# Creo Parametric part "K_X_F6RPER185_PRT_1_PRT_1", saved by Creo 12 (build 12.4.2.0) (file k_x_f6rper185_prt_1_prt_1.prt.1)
Units: Custom; MM, KILOGRAM, SECS

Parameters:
  PTC_WM_ITERATION = "0"
  PTC_WM_VERSION = "-.0"
  PTC_WM_LIFECYCLE_STATE = "In Work"
  PTC_WM_LIFECYCLE = "MO_CADDocument"
  PTC_WM_CREATED_BY = "Maximilian Roepper (Z0017RMS: MO)"
  PTC_WM_CREATED_ON = "18-Sep-26 11:36:42 AM"
  PTC_WM_MODIFIED_BY = "Maximilian Roepper (Z0017RMS: MO)"
  PTC_WM_MODIFIED_ON = "18-Sep-26 11:36:46 AM"
  PDMLINKNUMBER = "PDM000071455158"
  PTC_WM_NAME = "k_x_f6rper185_prt_1_prt_1.prt"
  PTC_WM_NUMBER = "PDM000071455158"

Other parameters: WEIGHT, WEIGHT_FACTOR, WEIGHT_ADD, _MASS_TEMP, _DIFF_TEMP, MC_ERRORS, SUPPLIER

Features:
  1. coordinate system
  2. datum plane "PRT_YZ"
  3. datum plane "PRT_XY"
  4. datum plane "PRT_XZ"
  5. coordinate system
  6. datum axis
  7. datum axis
  8. datum axis
  9. coordinate system
  10. imported feature
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
Other named items: PRT, SIEMENS_MO, DRW_VIEW_ORG, PRT_X, PRT_Y, PRT_Z, CS0, ROUGH_GROB

Layers: 00_STD_CSYS-KSYS, 01_STD_PLANES-EBENEN, 02_STD_AXES-ACHSEN, 03_STD_CSYS-KSYS, 24_IMPORT_FEAT-IMPORT_KE

Surfaces: 16 tabulated cylinder, 8 plane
